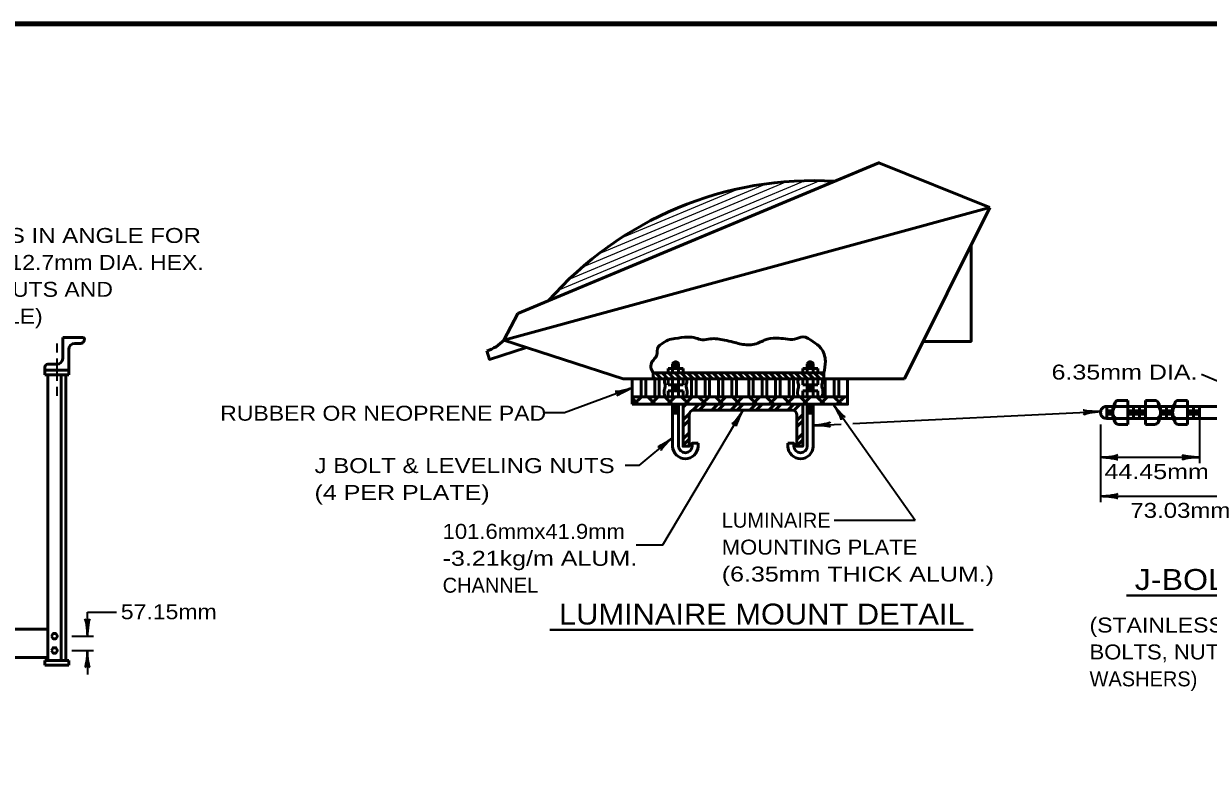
# Model space of a CAD drawing. Extents: x -94 to 762, y -50 to 494.
# Drawn here: x 194.5 to 432, y 335.4 to 487.4 of the extents above; entities that cross this region are included whole.
import ezdxf

# ---------------------------------------------------------------- set-up
doc = ezdxf.new("R2010")
doc.units = 0
doc.header["$LTSCALE"] = 1.2
doc.layers.add('1', color=7, linetype='Continuous', lineweight=53)

msp = doc.modelspace()

# ---------------------------------------------------------------- linework, layer by layer
at = {"layer": '1', "lineweight": 25}
for p, q in [((354.287, 455.902), (301.578, 433.873)), ((351.146, 455.89), (303.794, 436.1)), ((347.601, 455.709), (306.414, 438.495)), ((343.432, 455.267), (309.657, 441.152)), ((338.074, 454.328), (314.089, 444.305))]:
    msp.add_line(p, q, dxfattribs=at)
at = {"layer": '1'}
for p, q in [((371.114, 416.139), (388.248, 450.504)), ((290.747, 423.926), (293.564, 429.223)), ((202.279, 424.456), (202.279, 420.256)), ((202.279, 424.456), (206.479, 424.456)), ((204.679, 423.256), (205.879, 423.256)), ((203.479, 422.056), (203.479, 416.956)), ((198.679, 418.456), (198.679, 416.956)), ((201.079, 419.056), (199.279, 419.056)), ((323.714, 418.239), (323.714, 417.339)), ((323.714, 418.239), (326.714, 418.239)), ((324.613, 419.139), (325.814, 419.139)), ((324.913, 418.689), (325.514, 418.689)), ((325.814, 419.139), (325.814, 417.339)), ((326.714, 418.239), (326.714, 417.339)), ((350.714, 418.239), (350.714, 417.339)), ((350.714, 418.239), (353.714, 418.239)), ((351.614, 419.139), (351.614, 417.339)), ((351.614, 419.139), (352.814, 419.139)), ((351.913, 418.689), (352.514, 418.689)), ((352.814, 419.139), (352.814, 417.339)), ((353.714, 418.239), (353.714, 417.339)), ((203.479, 417.856), (198.679, 417.856)), ((203.479, 416.956), (198.679, 416.956)), ((199.279, 416.956), (199.279, 359.656)), ((201.979, 416.956), (201.979, 359.656)), ((202.879, 416.956), (202.879, 359.656)), ((314.714, 416.139), (320.714, 416.139)), ((316.514, 412.538), (316.514, 416.139)), ((318.314, 412.538), (318.314, 416.139)), ((319.214, 412.538), (319.214, 416.139)), ((321.131, 416.139), (320.714, 416.556)), ((321.014, 412.538), (321.014, 416.139)), ((322.404, 416.139), (321.204, 417.339)), ((321.913, 412.538), (321.913, 416.139)), ((323.677, 416.139), (322.477, 417.339)), ((323.714, 416.139), (323.714, 414.939)), ((324.949, 416.139), (323.749, 417.339)), ((326.222, 416.139), (325.022, 417.339)), ((325.814, 416.139), (325.814, 413.739)), ((327.495, 416.139), (326.295, 417.339)), ((326.714, 416.139), (326.714, 414.939)), ((328.768, 416.139), (327.568, 417.339)), ((328.408, 412.538), (328.408, 416.139)), ((330.041, 416.139), (328.841, 417.339)), ((329.308, 412.538), (329.308, 416.139)), ((331.313, 416.139), (330.113, 417.339)), ((331.108, 412.538), (331.108, 416.139)), ((332.586, 416.139), (331.386, 417.339)), ((332.008, 412.538), (332.008, 416.139)), ((333.859, 416.139), (332.659, 417.339)), ((333.808, 412.538), (333.808, 416.139)), ((335.132, 416.139), (333.932, 417.339)), ((334.708, 412.538), (334.708, 416.139)), ((336.405, 416.139), (335.205, 417.339)), ((337.677, 416.139), (336.477, 417.339)), ((336.508, 412.538), (336.508, 416.139)), ((337.408, 412.538), (337.408, 416.139)), ((338.95, 416.139), (337.75, 417.339)), ((340.223, 416.139), (339.023, 417.339)), ((339.872, 412.538), (339.872, 416.139)), ((341.496, 416.139), (340.296, 417.339)), ((340.772, 412.538), (340.772, 416.139)), ((342.769, 416.139), (341.569, 417.339)), ((342.572, 412.538), (342.572, 416.139)), ((344.041, 416.139), (342.841, 417.339)), ((343.472, 412.538), (343.472, 416.139)), ((345.314, 416.139), (344.114, 417.339)), ((345.272, 412.538), (345.272, 416.139)), ((346.587, 416.139), (345.387, 417.339)), ((346.172, 412.538), (346.172, 416.139)), ((347.86, 416.139), (346.66, 417.339)), ((349.132, 416.139), (347.933, 417.339)), ((347.972, 412.538), (347.972, 416.139)), ((348.872, 412.538), (348.872, 416.139)), ((350.405, 416.139), (349.205, 417.339)), ((351.678, 416.139), (350.478, 417.339)), ((350.714, 416.139), (350.714, 414.939)), ((352.951, 416.139), (351.751, 417.339)), ((352.814, 416.139), (352.814, 413.739)), ((354.224, 416.139), (353.024, 417.339)), ((353.714, 416.139), (353.714, 414.939)), ((354.913, 416.721), (354.297, 417.339)), ((354.913, 416.139), (371.114, 416.139)), ((355.214, 412.538), (355.214, 416.139)), ((357.014, 412.538), (357.014, 416.139)), ((357.913, 412.538), (357.913, 416.139)), ((359.714, 412.538), (359.714, 416.139)), ((323.714, 414.939), (326.714, 414.939)), ((323.714, 413.739), (326.714, 413.739)), ((323.714, 413.739), (323.714, 412.538)), ((324.613, 413.739), (324.613, 412.538)), ((324.913, 414.339), (325.514, 414.339)), ((325.814, 413.739), (325.814, 412.538)), ((326.714, 413.739), (326.714, 412.538)), ((350.714, 414.939), (353.714, 414.939)), ((350.714, 413.739), (353.714, 413.739)), ((350.714, 413.739), (350.714, 412.538)), ((351.614, 413.739), (351.614, 412.538)), ((351.913, 414.339), (352.514, 414.339)), ((352.814, 413.739), (352.814, 412.538)), ((353.714, 413.739), (353.714, 412.538)), ((317.727, 411.038), (316.514, 412.252)), ((316.841, 411.038), (318.341, 412.538)), ((321.121, 411.038), (319.621, 412.538)), ((320.235, 411.038), (321.735, 412.538)), ((324.515, 411.038), (323.015, 412.538)), ((323.63, 411.038), (325.13, 412.538)), ((327.909, 411.038), (326.409, 412.538)), ((327.024, 411.038), (328.524, 412.538)), ((331.303, 411.038), (329.803, 412.538)), ((330.418, 411.038), (331.918, 412.538)), ((334.697, 411.038), (333.197, 412.538)), ((333.812, 411.038), (335.312, 412.538)), ((338.092, 411.038), (336.592, 412.538)), ((337.206, 411.038), (338.706, 412.538)), ((341.486, 411.038), (339.986, 412.538)), ((340.6, 411.038), (342.1, 412.538)), ((344.88, 411.038), (343.38, 412.538)), ((343.994, 411.038), (345.494, 412.538)), ((348.274, 411.038), (346.774, 412.538)), ((347.388, 411.038), (348.888, 412.538)), ((351.668, 411.038), (350.168, 412.538)), ((350.782, 411.038), (352.282, 412.538)), ((355.062, 411.038), (353.562, 412.538)), ((354.177, 411.038), (355.677, 412.538)), ((358.456, 411.038), (356.956, 412.538)), ((357.571, 411.038), (359.071, 412.538)), ((414.076, 411.81), (415.876, 411.81)), ((415.876, 411.81), (415.876, 407.01)), ((419.476, 411.81), (419.476, 407.01)), ((421.276, 411.81), (419.476, 411.81)), ((426.076, 411.81), (427.876, 411.81)), ((427.876, 411.81), (427.876, 407.01)), ((324.613, 411.038), (324.613, 402.595)), ((324.613, 410.139), (325.814, 410.139)), ((324.613, 409.239), (325.814, 409.239)), ((324.913, 410.589), (325.514, 410.589)), ((324.913, 409.689), (325.514, 409.689)), ((325.814, 411.038), (325.814, 402.639)), ((326.714, 410.458), (327.294, 411.038)), ((326.714, 407.912), (327.942, 409.141)), ((328.609, 409.808), (329.84, 411.038)), ((328.814, 409.839), (348.614, 409.839)), ((329.912, 409.839), (331.112, 411.038)), ((332.458, 409.839), (333.658, 411.038)), ((333.731, 409.839), (334.931, 411.038)), ((336.276, 409.839), (337.476, 411.038)), ((337.549, 409.839), (338.749, 411.038)), ((340.095, 409.839), (341.295, 411.038)), ((341.368, 409.839), (342.567, 411.038)), ((343.913, 409.839), (345.113, 411.038)), ((345.186, 409.839), (346.386, 411.038)), ((347.731, 409.839), (348.931, 411.038)), ((348.936, 409.77), (350.204, 411.038)), ((349.514, 407.802), (350.714, 409.002)), ((351.614, 411.038), (351.614, 402.639)), ((352.814, 410.139), (351.614, 410.139)), ((352.814, 409.239), (351.614, 409.239)), ((352.514, 410.589), (351.913, 410.589)), ((352.514, 409.689), (351.913, 409.689)), ((352.814, 411.038), (352.814, 402.595)), ((411.676, 410.61), (411.676, 408.21)), ((412.276, 410.01), (412.276, 408.81)), ((412.876, 410.61), (412.876, 408.21)), ((416.476, 410.01), (416.476, 408.81)), ((417.076, 410.61), (417.076, 408.21)), ((417.676, 410.01), (417.676, 408.81)), ((418.276, 410.61), (418.276, 408.21)), ((418.876, 410.01), (418.876, 408.81)), ((422.476, 408.21), (422.476, 410.61)), ((423.076, 408.81), (423.076, 410.01)), ((423.676, 408.21), (423.676, 410.61)), ((424.276, 408.81), (424.276, 410.01)), ((424.876, 408.21), (424.876, 410.61)), ((428.476, 410.01), (428.476, 408.81)), ((429.076, 410.61), (429.076, 408.21)), ((429.676, 410.01), (429.676, 408.81)), ((430.276, 410.61), (430.276, 408.21)), ((326.714, 406.64), (327.913, 407.84)), ((349.514, 406.529), (350.714, 407.729)), ((411.676, 408.21), (412.876, 408.21)), ((414.076, 407.01), (415.876, 407.01)), ((421.276, 407.01), (419.476, 407.01)), ((426.076, 407.01), (427.876, 407.01)), ((326.714, 404.094), (327.913, 405.294)), ((326.714, 402.821), (327.913, 404.021)), ((349.514, 403.984), (350.714, 405.184)), ((327.804, 402.639), (327.913, 402.749)), ((329.714, 403.239), (329.714, 402.595)), ((347.714, 403.239), (347.714, 402.595)), ((349.514, 402.711), (350.714, 403.911)), ((164.179, 365.956), (199.279, 365.956)), ((164.179, 360.256), (199.279, 360.256)), ((198.679, 359.656), (198.679, 358.756)), ((203.479, 359.656), (203.479, 358.756)), ((203.479, 358.756), (198.679, 358.756))]:
    msp.add_line(p, q, dxfattribs=at)
at = {"layer": '1', "lineweight": 35}
for p, q in [((201.079, 423.256), (201.079, 421.456)), ((201.079, 420.256), (201.079, 415.756)), ((434.505, 415.41), (430.717, 417.026)), ((201.079, 414.556), (201.079, 412.756)), ((356.828, 411.038), (373.235, 387.822)), ((360.781, 407.2), (410.435, 409.588)), ((352.814, 406.817), (358.383, 407.084)), ((410.422, 407.01), (410.422, 391.41)), ((430.276, 408.21), (430.276, 399.21)), ((410.422, 400.41), (430.276, 400.41)), ((410.422, 392.61), (443.476, 392.61)), ((357.037, 387.822), (373.235, 387.822)), ((207.229, 364.531), (207.229, 369.331)), ((207.229, 369.331), (213.036, 369.331)), ((204.079, 364.531), (208.429, 364.531)), ((204.079, 361.681), (208.429, 361.681)), ((207.229, 361.681), (207.229, 356.881))]:
    msp.add_line(p, q, dxfattribs=at)
at = {"layer": '1', "lineweight": 40}
for p, q in [((415.621, 372.674), (440.27, 372.674)), ((299.98, 365.781), (384.919, 365.781))]:
    msp.add_line(p, q, dxfattribs=at)
at = {"layer": '1', "lineweight": 158}
msp.add_lwpolyline([(755.402, 487.372), (-36.298, 487.272), (-36.198, -38.728)], dxfattribs=at)
at = {"layer": '1'}
for points in [[(388.248, 450.504), (365.995, 459.495), (293.564, 429.223)], [(314.714, 416.139), (290.747, 423.926), (388.248, 450.504)], [(374.862, 423.656), (384.462, 423.656), (384.462, 442.911)], [(295.312, 422.442), (287.894, 420.032), (287.338, 421.744)], [(324.613, 419.139), (324.613, 418.239), (324.613, 417.339)], [(324.613, 416.139), (324.613, 414.939), (324.613, 413.739)], [(351.614, 416.139), (351.614, 414.939), (351.614, 413.739)], [(326.714, 411.038), (326.714, 402.639), (327.913, 402.639), (327.913, 408.939)], [(349.514, 408.939), (349.514, 402.639), (350.714, 402.639), (350.714, 411.038), (326.714, 411.038)], [(411.676, 410.61), (412.876, 410.61), (443.476, 410.61)], [(412.876, 408.21), (422.303, 408.21), (425.05, 408.21), (443.311, 408.21)], [(329.714, 403.239), (328.514, 403.239), (328.514, 402.639)], [(347.714, 403.239), (348.913, 403.239), (348.913, 402.639)], [(203.479, 359.656), (201.979, 359.656), (198.679, 359.656)]]:
    msp.add_lwpolyline(points, dxfattribs=at)
for points in [[(320.714, 416.139), (320.714, 417.339), (354.913, 417.339), (354.913, 416.139)], [(316.514, 411.038), (316.514, 412.538), (359.714, 412.538), (359.714, 411.038), (350.714, 411.038), (326.714, 411.038)], [(200.029, 364.531), (200.329, 365.05), (200.929, 365.05), (201.229, 364.531), (200.929, 364.011), (200.329, 364.011)], [(200.029, 361.681), (200.329, 362.201), (200.929, 362.201), (201.229, 361.681), (200.929, 361.161), (200.329, 361.161)]]:
    msp.add_lwpolyline(points, close=True, dxfattribs=at)
at = {"layer": '1', "lineweight": 35}
for points in [[(316.514, 414.339), (302.904, 409.319), (298.817, 409.319)], [(338.714, 409.839), (322.566, 382.758), (317.283, 382.758)], [(324.613, 404.363), (317.799, 398.749), (315.108, 398.749)]]:
    msp.add_lwpolyline(points, dxfattribs=at)
at = {"layer": '1'}
for centre, radius, start, end in [((352.993, 384.924), 70.989, 86.65304, 138.7098), ((204.679, 422.056), 1.2, 90, 180), ((205.874, 424.008), 0.752, 270.36838, 36.50153), ((285.216, 428.814), 7.381, 286.70309, 318.52939), ((199.279, 418.456), 0.6, 90, 180), ((201.079, 420.256), 1.2, 270, 0), ((325.214, 418.92), 0.638, 19.9738, 160.0262), ((352.214, 418.92), 0.638, 19.9738, 160.0262), ((417.117, 409.41), 4.24, 151.86684, 208.13316), ((414.028, 411.085), 0.727, 86.18406, 220.68583), ((421.325, 411.085), 0.727, 319.31417, 93.81594), ((418.236, 409.41), 4.24, 331.86684, 28.13316), ((429.117, 409.41), 4.24, 151.86684, 208.13316), ((426.028, 411.085), 0.727, 86.18406, 220.68583), ((328.814, 408.939), 0.9, 90, 180), ((348.614, 408.939), 0.9, 0, 90), ((411.623, 409.41), 1.201, 87.44352, 272.55648), ((414.376, 409.41), 1.5, 126.8699, 233.1301), ((420.976, 409.41), 1.5, 306.8699, 53.1301), ((426.376, 409.41), 1.5, 126.8699, 233.1301), ((414.028, 407.736), 0.727, 139.31417, 273.81594), ((421.325, 407.736), 0.727, 266.18406, 40.68583), ((426.028, 407.736), 0.727, 139.31417, 273.81594), ((327.164, 402.688), 2.551, 182.09574, 357.90426), ((327.164, 402.688), 1.351, 182.09574, 357.90426), ((350.263, 402.688), 2.551, 182.09574, 357.90426), ((350.263, 402.688), 1.351, 182.09574, 357.90426)]:
    msp.add_arc(centre, radius, start, end, dxfattribs=at)
at = {"layer": '1', "lineweight": 40}
for centre, major_axis, ratio, start_param, end_param in [((315.17, 414.196), (2.075, 0.566), 0.122415, 3.1415927, 5.386832), ((315.34, 413.635), (1.905, 0.927), 0.07063, 0.8650754, 3.1424706), ((357.855, 410.16), (-1.39, 1.642), 0.122415, 0.8963533, 3.1415927), ((357.855, 410.16), (-1.39, 1.642), 0.122415, 0.8963533, 3.1415927), ((337.758, 408.884), (1.258, 1.745), 0.122415, 3.1415927, 5.386832), ((338.243, 408.554), (0.898, 1.918), 0.07063, 0.8650754, 3.1424706), ((357.397, 409.794), (1.044, -1.843), 0.07063, 6.2823074, 8.5597026), ((357.397, 409.794), (1.044, -1.843), 0.07063, 6.2823074, 8.5597026), ((409.08, 409.777), (-2.115, 0.109), 0.07063, 6.2823074, 8.5597026), ((409.143, 409.194), (2.131, 0.29), 0.122415, 0.8963533, 3.1415927), ((354.105, 407.211), (-2.131, -0.29), 0.122415, 0.8963533, 3.1415927), ((354.169, 406.628), (2.115, -0.109), 0.07063, 6.2823074, 8.5597026), ((323.414, 403.704), (-1.761, -1.177), 0.07063, 6.2823074, 8.5597026), ((323.414, 403.704), (-1.761, -1.177), 0.07063, 6.2823074, 8.5597026), ((323.814, 403.274), (1.535, 1.507), 0.122415, 0.8963533, 3.1415927), ((323.814, 403.274), (1.535, 1.507), 0.122415, 0.8963533, 3.1415927), ((411.766, 400.156), (-2.108, 0.211), 0.07063, 3.1407148, 5.41811), ((411.766, 400.156), (-2.108, 0.211), 0.07063, 3.1407148, 5.41811), ((411.731, 400.742), (-2.143, -0.187), 0.122415, 0.8963533, 3.1415927), ((411.731, 400.742), (-2.143, -0.187), 0.122415, 0.8963533, 3.1415927), ((428.967, 400.079), (2.143, 0.187), 0.122415, 0.8963533, 3.1415927), ((428.967, 400.079), (2.143, 0.187), 0.122415, 0.8963533, 3.1415927), ((428.932, 400.664), (2.108, -0.211), 0.07063, 3.1407148, 5.41811), ((428.932, 400.664), (2.108, -0.211), 0.07063, 3.1407148, 5.41811), ((411.766, 392.356), (-2.108, 0.211), 0.07063, 3.1407148, 5.41811), ((411.766, 392.356), (-2.108, 0.211), 0.07063, 3.1407148, 5.41811), ((411.731, 392.942), (-2.143, -0.187), 0.122415, 0.8963533, 3.1415927), ((411.731, 392.942), (-2.143, -0.187), 0.122415, 0.8963533, 3.1415927), ((206.898, 365.84), (0.187, -2.143), 0.122415, 0.8963533, 3.1415927), ((206.898, 365.84), (0.187, -2.143), 0.122415, 0.8963533, 3.1415927), ((207.483, 365.876), (-0.211, -2.108), 0.07063, 3.1407148, 5.41811), ((207.483, 365.876), (-0.211, -2.108), 0.07063, 3.1407148, 5.41811), ((206.975, 360.336), (0.211, 2.108), 0.07063, 3.1407148, 5.41811), ((207.561, 360.371), (-0.187, 2.143), 0.122415, 0.8963533, 3.1415927)]:
    msp.add_ellipse(centre, major_axis=major_axis, ratio=ratio, start_param=start_param, end_param=end_param, dxfattribs=at)
at = {"layer": '1'}
for points in [[(320.714, 417.339), (320.231, 418.435), (320.53, 419.63), (321.377, 420.776), (321.775, 422.619), (322.423, 423.167), (323.668, 423.914), (325.062, 424.213), (327.602, 424.512), (329.245, 424.313), (330.54, 423.964), (332.133, 424.163), (335.022, 423.914), (336.765, 423.516), (339.354, 422.968), (341.994, 423.416), (342.99, 423.914), (345.43, 424.313), (347.272, 424.163), (349.065, 424.114), (350.758, 424.562), (352.75, 423.615), (354.344, 422.32), (355.24, 419.68), (354.913, 417.339)], [(322.995, 416.119), (322.995, 415.87), (322.959, 415.407), (323.102, 414.979), (323.102, 414.694), (323.066, 414.338), (322.959, 414.018), (322.924, 413.697), (322.888, 413.448), (322.959, 412.913), (322.995, 412.593)], [(327.432, 416.119), (327.432, 415.87), (327.468, 415.407), (327.325, 414.979), (327.325, 414.694), (327.361, 414.338), (327.468, 414.018), (327.503, 413.697), (327.539, 413.448), (327.468, 412.913), (327.432, 412.593)], [(349.774, 416.132), (349.774, 415.882), (349.738, 415.419), (349.881, 414.992), (349.881, 414.707), (349.845, 414.351), (349.738, 414.03), (349.703, 413.71), (349.667, 413.46), (349.738, 412.926), (349.774, 412.605)], [(354.653, 416.132), (354.653, 415.882), (354.689, 415.419), (354.546, 414.992), (354.546, 414.707), (354.582, 414.351), (354.689, 414.03), (354.724, 413.71), (354.76, 413.46), (354.689, 412.926), (354.653, 412.605)]]:
    msp.add_spline(points, degree=3, dxfattribs=at)

# ---------------------------------------------------------------- texts
for s, height, width, p in [('(2) 14.29mm DIA. HOLES IN ANGLE FOR', 3, 1.2, (139.041, 443.399)), ('ATTACHING CHANNEL, 12.7mm DIA. HEX.', 3, 1.15, (139.041, 437.999)), ('HD. STN. STL. BOLTS, NUTS AND', 3, 1.15, (139.041, 432.599)), ('WASHERS. (2 PER ANGLE)', 3, 1.15, (139.041, 427.199)), ('6.35mm DIA.', 3, 1.25, (400.612, 416.002)), ('RUBBER OR NEOPRENE PAD', 3, 1.15, (233.867, 407.752)), ('J BOLT & LEVELING NUTS', 3, 1.2, (252.786, 397.247)), ('44.45mm', 3, 1.25, (411.243, 396.037)), ('(4 PER PLATE)', 3, 1.25, (252.786, 391.847)), ('73.03mm', 3, 1.2, (416.415, 388.266)), ('101.6mmx41.9mm', 3, 1.1, (278.482, 384.054)), ('MOUNTING PLATE', 3, 1.1, (334.464, 380.898)), ('-3.21kg/m ALUM.', 3, 1.25, (278.482, 378.654)), ('(6.35mm THICK ALUM.)', 3, 1.25, (334.464, 375.498)), ('J-BOLT', 4.2, 1.15, (417.287, 373.805)), ('57.15mm', 3, 1.15, (213.931, 367.934)), ('LUMINAIRE MOUNT DETAIL', 4.2, 1.1, (301.826, 366.871)), ('(STAINLESS STEEL', 3, 1.15, (408.23, 365.273)), ('BOLTS, NUTS, AND', 3, 1.1, (408.23, 359.873))]:
    msp.add_text(s, height=height, dxfattribs=dict(at, width=width)).set_placement(p)
for s, p in [('LUMINAIRE', (334.464, 386.298)), ('CHANNEL', (278.482, 373.254)), ('WASHERS)', (408.23, 354.473))]:
    msp.add_text(s, height=3, dxfattribs=at).set_placement(p)

doc.saveas('drawing.dxf')
